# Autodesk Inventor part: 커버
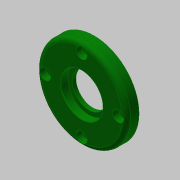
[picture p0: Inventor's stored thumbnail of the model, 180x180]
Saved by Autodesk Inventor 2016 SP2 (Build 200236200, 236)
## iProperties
Created: 2019-09
Part Number: 커버
Material: 알루미늄 6061
Document SubType Name: Modeling
Designer: mduedu
Density: 2.71 g/cm^3
Mass: 60.8496 g
Surface Area: 89.5893 cm^2
Volume: 22.4537 cm^3
Appearance: 진녹색
Author: mduedu
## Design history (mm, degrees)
sketch "스케치1"
  geometry: C1 r 32 at (0, 0); 1 further point
  constraints: 1 centre point, 1 coincident
  dimensions: "d0" = 64 diameter of C1
extrude "돌출1" new body sketch "스케치1" distance "d1" = 9; taper "d2" = 0 deg
sketch "스케치2"
  geometry: C1 r 21 at (0, 0); 1 further point
  constraints: 1 centre point, 1 coincident
  dimensions: "d3" = 42 diameter of C1
extrude "돌출2" join sketch "스케치2" distance "d4" = 3; taper "d5" = 0 deg
hole "구멍1" diameter "d8" = 24; stored, may be unused: countersink angle "d12" = 90 deg, drill point angle "d14" = 118 deg; dims "d6" = 10, "d7" = 10, "d9" = 6, "d10" = 30, "d11" = 5.2, "d13" = 8
hole "구멍2" diameter "d17" = 37; stored, may be unused: countersink angle "d21" = 90 deg, drill point angle "d23" = 0 deg; dims "d15" = 10, "d16" = 10, "d18" = 6, "d19" = 30, "d20" = 5.2, "d22" = 4
fillet "모깎기1" dims "d24" = 3
fillet "모깎기2" dims "d25" = 3
chamfer "모따기1" distance "d27" = 0.5; stored, may be unused: second distance "d28" = 2, angle "d29" = 30 deg
chamfer "모따기2" distance "d30" = 1; stored, may be unused: second distance "d31" = 2, angle "d32" = 30 deg
sketch "스케치3" dims "d33" = 52
  geometry: 3 further points
  constraints: 2 vertical alignment, 1 coincident, 2 other
hole "구멍3" sketch "스케치3" at (0, 26) diameter "d34" = 4.5; stored, may be unused: countersink angle "d38" = 90 deg, drill point angle "d40" = 0 deg; dims "d35" = 6, "d36" = 8, "d37" = 4.4, "d39" = 4
node "솔리드1"
pattern_circular "원형 패턴1" dims angle "d42" = 360 deg
